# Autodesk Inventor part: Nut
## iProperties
Created: 2002-02
Part Number: Nut
Document SubType Name: Modeling
Designer: ***
Control State: 0
Master: False
Checked Out: False
Shininess: 77.0
Length Units: 11269
Angle Units: 11279
Time Units: 11290
Mass Units: 11283
Length Display Precision: 3
Angle Display Precision: 2
Density: 0.0
Volumn: 0.0
Area: 0.0
PropertySet Name: Model Information
Author: ***
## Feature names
1. Extrusion1
2. Fillet1
3. Extrusion2
4. Hole1
